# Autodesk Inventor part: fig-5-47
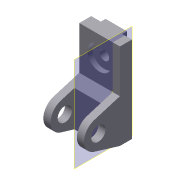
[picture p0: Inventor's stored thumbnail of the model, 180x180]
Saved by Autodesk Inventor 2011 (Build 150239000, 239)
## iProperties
Shininess: 65.0
Angle Display Precision: 2
Document Length Units: 11269
Document Angle Units: 11279
Document Time Units: 11290
Document Mass Units: 11283
Document Length Units Precision: 3
Document Angle Units Precision: 2
Created: 2001-11
Part Number: fig-5-47
Document SubType Name: Modeling
Designer: Renu Muthoo
Density: 1 g/cm^3
Density: 0.0
Volumn: 0.0
Area: 0.0
PropertySet Name: Model Information
Control State: 0
Master: False
Checked Out: False
Author: Renu Muthoo
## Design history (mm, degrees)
node "Sketch1"
sketch "Sketch2"
  geometry: L1 (33.257, 104.664)-(33.257, -75.336); L2 (33.257, -75.336)-(8.257, -75.336); L3 (8.257, -75.336)-(-45.451, -59.045); L4 (-45.451, -1.628)-(8.257, 14.664); L5 (8.257, 14.664)-(8.257, 104.664); L6 (8.257, 104.664)-(33.257, 104.664); C1 r 15 at (-36.743, -30.336); A1 r 30 centre (-36.743, -30.336) between (-45.451, -1.628) and (-45.451, -59.045)
  constraints: 12 end point, 2 centre point, 2 equal length, 2 parallel, 2 point on circle, 2 tangent, 1 coincident, 1 perpendicular, 1 vertical
  dimensions: "d0" = 180 distance of L1.start L1.end; "d1" = 30 radius of A1; "d2" = 25 distance of L5.end L1.start; "d3" = 45 distance from line of L2 A1.centre; "d4" = 70 distance from line of L1 A1.centre; "d5" = 30 diameter of C1
extrude "Extrusion1" new body sketch "Sketch2" distance "d6" = 85; taper "d7" = 0 deg
workplane "Work Plane1"
sketch "Sketch3"
  geometry: L1 (15, 62.364)-(70, 62.364); L2 (70, 62.364)-(70, -52.386); L3 (70, -52.386)-(15, -52.386); L4 (15, -52.386)-(15, 62.364); L5 (0, -45)-(0, -28.708) reference
  constraints: 8 end point, 2 parallel, 1 horizontal, 1 perpendicular
  dimensions: "d8" = 55 distance of L1.start L1.end; "d9" = 15 distance between parallel lines of L5 L4
extrude "Extrusion2" cut sketch "Sketch3" distance "d10" = 50; taper "d11" = 0 deg
sketch "Sketch4"
  geometry: L1 (0, 25)-(85, 25) reference; L2 (0, 0)-(0, 25) reference; L3 (20, 25)-(65, 25); L4 (65, 25)-(65, 35); L5 (65, 35)-(20, 35); L6 (20, 35)-(20, 25)
  constraints: 8 end point, 2 parallel, 1 horizontal, 1 perpendicular, 1 point on line
  dimensions: "d12" = 45 distance of L4.end L5.end; "d13" = 10 distance of L3.end L4.end; "d14" = 20 distance between parallel lines of L2 L6
extrude "Extrusion3" join sketch "Sketch4" stored distance "d15" = 50; taper "d16" = 0 deg
sketch "Sketch5"
  geometry: L1 (85, 0)-(85, 90) reference; L2 (0, 90)-(85, 90) reference; 1 further point
  dimensions: "d17" = 42 distance from line of L2 point (42.5, 48); "d18" = 42.5 distance from line of L1 point (42.5, 48)
hole "Hole1" sketch "Sketch5" at (42.5, 48) diameter "d19" = 20; stored, may be unused: countersink angle "d23" = 82 deg, drill point angle "d25" = 118 deg; dims "d20" = 6, "d21" = 50, "d22" = 10, "d24" = 8
workplane "Work Plane7"
workpoint "Work Point7"
workpoint "Work Point8"
body "Solid1"
other parameters: "d29" = 0
